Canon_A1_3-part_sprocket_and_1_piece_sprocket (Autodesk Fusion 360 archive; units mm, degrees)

design "Canon A1 3-part sprocket and 1 piece sprocket" references "Canon A1 Sprocket V2 real"
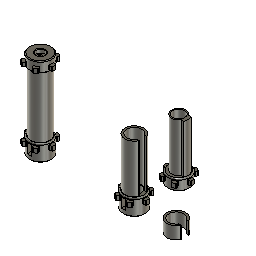
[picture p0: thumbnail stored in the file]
part number: 2026-03-01-16-37-55-654
sketch "Sketch1" plane through (0, 0, 0) normal (0, 0, 1) x axis (1, 0, 0)
  line L1 (4.3, 0) -> (4.5, 0)
  line L2 (4.45, 0) -> (4.3, 0)
  line L3 (5.6, 0.975) -> (4.45, 0.975)
  line L4 (5.6, -0.975) -> (5.6, 0.975)
  line L5 (4.45, -0.975) -> (5.6, -0.975)
  line L6 (4.3419, 0.975) -> (4.45, 0.975)
  line L7 (4.3419, -0.975) -> (4.45, -0.975)
  line L8 (5.6, 0.75) -> (5.6, 0)
  line L9 (4.6423, 0.975) -> (5.6, 0.75)
  line L10 (4.6423, -0.975) -> (5.6, -0.75)
  circle C1 centre (0, 0) radius 4.45
  circle C2 centre (0, 0) radius 1.725
  point P1 (0, 0)
  point P2 (0, 0)
  point P3 (0, 0)
  point P6 (4.45, 0)
  point P7 (4.45, 0.975)
  point P8 (4.45, -0.975)
  point P12 (4.3419, 0.975)
  point P13 (4.3419, -0.975)
  point P14 (5.6, 0)
  point P16 (4.6423, 0.975)
  point P15 (5.6, 0.75)
  point P17 (5.6, -0.75)
  point P18 (4.6423, -0.975)
  point P9 (5.6, 0.975)
  point P11 (4.45, -0.975)
  coincident P1 P2
  coincident P1 P3
  horizontal L1
  coincident L1 P6
  coincident C1 P6
  symmetric L1 P7 P8
  horizontal L3
  vertical L4
  horizontal L5
  coincident C1 P12
  coincident C1 P13
  midpoint L4 P14
  parallel L4 L8
  coincident L3 P16
  symmetric L1 P15 P17
  symmetric L1 P16 P18
  dimension "d1" diameter C1 = 8.9
  dimension "d2" diameter C2 = 3.45
  dimension "d3" distance P6 P7 = 0.975
  dimension "d4" distance P7 P9 = 1.15
  dimension "d5" distance P7 P11 = 1.95
  dimension "d6" distance P14 P15 = 0.75
extrude "Extrude1" new body sketch "Sketch1" profile of C1 C2 along normal blind 4.4
extrude "Extrude2" add sketch "Sketch1" profile of C1 L3 L4 L5 L6 L7 L8 L9 L10 along normal blind 0.85
extrude "Extrude3" add of existing geometry blind 1.7
extrude "Extrude4" cut sketch "Sketch1" profile of C1 L3 L4 L5 L6 L7 L8 L9 L10 along normal blind 0.5
extrude "Extrude5" cut of existing geometry blind -0.15
extrude "Extrude6" add of existing geometry blind 0.15
extrude "Extrude8" cut of existing geometry blind -0.15
extrude "Extrude9" cut of existing geometry blind -0.2
split "Split1"
fillet "Fillet1" radius 0.2
fillet "Fillet2" radius 1
circular_pattern "C-Pattern1" TotalAngle 360
extrude "Extrude10" add sketch "Sketch1" profile of C2 along normal blind 3
sketch "Sketch2" plane through (0, 0, 3) normal (0, 0, 1) x axis (-1, 0, 0)
  line L1 (-1.05, -0.7) -> (1.05, -0.7)
  line L2 (-1.05, 0.7) -> (-1.05, -0.7)
  line L3 (1.05, 0.7) -> (-1.05, 0.7)
  line L4 (1.05, -0.7) -> (1.05, 0.7)
  line L5 (-1.05, 0.7) -> (1.05, -0.7)
  line L6 (1.05, 0.7) -> (-1.05, -0.7)
  circle C1 centre (0, 0) radius 1.725
  point P7 (0, 0)
  point P2 (0, 0)
  point P5 (-1.05, 0.7)
  point P6 (1.05, 0.7)
  point P4 (-1.05, -0.7)
  horizontal L1
  perpendicular L1 L2
  parallel L1 L3
  parallel L2 L4
  coincident L5 P7
  coincident L6 P7
  coincident P2 P7
  dimension "d33" distance P5 P6 = 2.1
  dimension "d34" distance P4 P5 = 1.4
extrude "Extrude11" cut sketch "Sketch2" profile of L1 L2 L3 L4 against normal blind 6.8
fillet "Fillet3" radius 0.3
fillet "Fillet4" radius 0.3
fillet "Fillet5" radius 0.5
combine "Combine1"
copy_paste_bodies "CopyPasteBodies1"
move "Move1"
move "Move2"
align "Align1"
move "Move3"
sketch "Sketch3" plane through (0, 0, 4.4) normal (0, 0, 1) x axis (-1, 0, 0)
  line L1 (-1.05, 0.7) -> (-1.05, -0.7)
  line L2 (1.05, 0.7) -> (-1.05, 0.7)
  line L3 (1.05, -0.7) -> (1.05, 0.7)
  line L4 (-1.05, -0.7) -> (1.05, -0.7)
  circle C1 centre (0, 0) radius 3.95
  circle C2 centre (0, 0) radius 3.81
  concentric C1 C2
  dimension "d43" diameter C2 = 7.62
extrude "Extrude12" add sketch "Sketch3" profile of L1 L2 L3 L4 C2 along normal blind 26.7
sketch "Sketch4" plane through (0, 0, 0) normal (0, 0, -1) x axis (1, 0, 0)
  circle C1 centre (0, 0) radius 2.025
  circle C2 centre (0, 0) radius 4.15
  circle C3 centre (0, 0) radius 4.45
  circle C4 centre (0, 0) radius 3.6
  circle C5 centre (0, 0) radius 2.6
  point P1 (0, 0)
  point P3 (0, 0)
  coincident P1 P3
  dimension "d46" diameter C3 = 8.9
  dimension "d47" = -0.85
  dimension "d50" = -1
extrude "Extrude13" cut sketch "Sketch4" profile of C1 C4 against normal blind 0.92
delete_face "DeleteFace1"
extrude "Extrude14" cut sketch "Sketch4" profile of C1 C5 against normal blind 7
extrude "Extrude15" add of existing geometry blind 2.2
extrude "Extrude16" add of existing geometry blind 2.2
align "Align2"
move "Move4"
align "Align3"
delete_face "DeleteFace2"
split "Split2"
move "Move5"
extrude "Extrude17" cut of existing geometry blind -2.2
align "Align4"
combine "Combine2"
extrude "Extrude18" add of existing geometry blind 8.28
extrude "Extrude19" cut sketch "Sketch4" profile of C1 C5 against normal blind 32.5
sketch "Sketch5" plane through (0, 0, 0.92) normal (0, 0, -1) x axis (1, 0, 0)
  circle C1 centre (0, 0) radius 2.6
  circle C2 centre (0, 0) radius 3.6
  circle C3 centre (0, 0) radius 2.7
  dimension "d63" = 0.1
extrude "Extrude20" cut sketch "Sketch5" profile of C1 C3 against normal blind 31.58
sketch "Sketch6" plane through (0, 0, 0) normal (0, 0, -1) x axis (1, 0, 0)
  circle C1 centre (0, 0) radius 3.6
  circle C2 centre (0, 0) radius 4.45
sketch "Sketch7" plane through (0, 0, 5.75) normal (0, 0, 1) x axis (-1, 0, 0)
  line L1 (-3.0153, 3.2727) -> (-3.1076, 3.4325)
  line L2 (-1.4188, 4.4075) -> (-1.3266, 4.2477)
  line L3 (-2.042, 5.1093) -> (-1.5561, 4.5923)
  line L4 (-3.3123, 4.554) -> (-2.2877, 5.1455)
  line L5 (-3.199, 3.6438) -> (-3.4038, 4.323)
  arc A1 centre (-2.2415, 3.9325) radius 1 clockwise from (-3.1076, 3.4325) to (-3.199, 3.6438)
  arc A2 centre (0, 0) radius 4.45 clockwise from (-3.0153, 3.2727) to (-1.3266, 4.2477)
  arc A3 centre (-2.2848, 3.9075) radius 1 clockwise from (-1.5561, 4.5923) to (-1.4188, 4.4075)
  arc A4 centre (-2.1877, 4.9723) radius 0.2 clockwise from (-2.2877, 5.1455) to (-2.042, 5.1093)
  arc A5 centre (-3.2123, 4.3808) radius 0.2 clockwise from (-3.4038, 4.323) to (-3.3123, 4.554)
sketch "Sketch8" plane through (0, 0, 0) normal (0, 0, -1) x axis (1, 0, 0)
  line L1 (-0.85, 4.5) -> (0, 4.5)
  line L2 (0.85, 4.5) -> (-0.85, 4.5)
  line L3 (0.85, 2.2) -> (0.85, 4.5)
  line L4 (-0.85, 2.2) -> (0.85, 2.2)
  line L5 (-0.85, 4.5) -> (-0.85, 2.2)
  point P2 (0, 4.5)
  point P3 (-0.85, 4.5)
  point P4 (0.85, 4.5)
  horizontal L1
  horizontal L2
  vertical L3
  horizontal L4
  vertical L5
  dimension "d66" distance P2 P3 = 0.85
  dimension "d67" distance P3 P4 = 1.7
extrude "Extrude21" cut sketch "Sketch8" against normal blind 5.75
sketch "Sketch9" plane through (0, 0, 0) normal (0, 0, -1) x axis (1, 0, 0)
  line L1 (0.85, 3.4982) -> (0.85, 4.3681)
  line L2 (-0.85, 4.3681) -> (-0.85, 3.4982)
  arc A1 centre (0, 0) radius 3.6 clockwise from (0.85, 3.4982) to (-0.85, 3.4982)
  arc A2 centre (0, 0) radius 4.45 clockwise from (0.85, 4.3681) to (-0.85, 4.3681)
  circle C1 centre (0, 0) radius 4.45
  circle C2 centre (0, 0) radius 3.6
  concentric A1 C1
  concentric A1 C2
extrude "Extrude22" add sketch "Sketch9" profile of L1 L2 C1 C2 against normal blind 1.9
sketch "Sketch10" plane through (0, 0, 0.92) normal (0, 0, -1) x axis (1, 0, 0)
  line L1 (0.85, 2.5627) -> (0.85, 3.4982)
  line L2 (-0.85, 3.4982) -> (-0.85, 2.5627)
  arc A1 centre (0, 0) radius 2.7 clockwise from (0.85, 2.5627) to (-0.85, 2.5627)
  arc A2 centre (0, 0) radius 3.6 clockwise from (0.85, 3.4982) to (-0.85, 3.4982)
  circle C1 centre (0, 0) radius 2.7
  circle C2 centre (0, 0) radius 3.6
  point P1 (0, 0)
  point P7 (0, 0)
  coincident P1 P7
  concentric C1 C2
extrude "Extrude23" add sketch "Sketch10" profile of L1 L2 C1 C2 against normal blind 0.98
sketch "Sketch11" plane through (0, 0, 35.5) normal (0, 0, 1) x axis (-1, 0, 0)
  circle C1 centre (0, 0) radius 4.15
  circle C2 centre (0, 0) radius 1.725
  circle C3 centre (0, 0) radius 1.775
  dimension "d74" = 0.05
extrude "Extrude24" cut sketch "Sketch11" profile of C2 C3 against normal blind 1.4
fillet "Fillet6" radius 0.3
copy_paste_bodies "CopyPasteBodies2"
move "Move9"
sketch "Sketch12" plane through (0, 0, 0) normal (0, 1, 0) x axis (1, 0, 0)
  line L1 (0, -17.75) -> (0, 0)
  line L2 (0, -19.75) -> (0, -17.75)
  line L3 (0, -15.75) -> (0, -17.75)
  line L4 (5, -15.75) -> (0, -15.75)
  line L5 (-5, -19.75) -> (0, -19.75)
  point P1 (0, 0)
  point P2 (0, 0)
  point P3 (0, -17.75)
  point P4 (0, -19.75)
  point P5 (0, -15.75)
  coincident P1 P2
  vertical L1
  vertical L2
  parallel L1 L3
  perpendicular L1 L4
  perpendicular L2 L5
  dimension "d79" distance P2 P3 = 17.75
  dimension "d80" distance P3 P4 = 2
  dimension "d81" distance P3 P5 = 2
split "Split3"
move "Move6"
move "Move7"
align "Align5"
fillet "Fillet7" radius 0.3
chamfer "Chamfer1" distance 0.2
fillet "Fillet8" radius 0.2
move "Move8"
copy_paste_bodies "CopyPasteBodies3"
move "Move10"
split "Split4"
move "Move11"
align "Align6" sketch "Sketch10"
move "Move12"
extrude "Extrude25" cut of existing geometry blind -5
extrude "Extrude26" add of existing geometry blind 20.9
sketch "Sketch13" plane through (0, 0, 23.9) normal (0, 0, 1) x axis (-1, 0, 0)
  circle C1 centre (-38, -43) radius 3.81
  circle C2 centre (-38, -43) radius 2.7
  circle C3 centre (-38, -43) radius 2.1
  concentric C1 C3
  dimension "d91" diameter C3 = 4.2
extrude "Extrude27" add sketch "Sketch13" profile of C2 C3 against normal blind 20.9
sketch "Sketch14" plane through (0, 0, 27.5) normal (0, 0, 1) x axis (-1, 0, 0)
  circle C1 centre (-38, -25) radius 2.7
  circle C2 centre (-38, -25) radius 3.95
  circle C3 centre (-38, -25) radius 3
  concentric C1 C3
extrude "Extrude28" cut sketch "Sketch14" profile of C1 C3 against normal blind 20.9
sketch "Sketch15" plane through (0, 0, 23.9) normal (0, 0, 1) x axis (-1, 0, 0)
  line L1 (-40.4819, -44.5) -> (-41, -44.5)
  line L2 (-40.4819, -41.5) -> (-41, -41.5)
  line L3 (-41.5023, -41.5) -> (-41, -41.5)
  line L4 (-41.5023, -44.5) -> (-41, -44.5)
  circle C1 centre (-38, -43) radius 2.1
  circle C2 centre (-38, -43) radius 3.81
  circle C3 centre (-38, -43) radius 2.9
  circle C4 centre (-38, -43) radius 3.81
  point P5 (-40.4819, -44.5)
  point P7 (-40.4819, -41.5)
  point P8 (-41.5023, -41.5)
  point P9 (-41.5023, -44.5)
  concentric C1 C3
  coincident C3 P5
  horizontal L1
  coincident C3 P7
  parallel L1 L2
  coincident C2 P8
  parallel L2 L3
  coincident C2 P9
  parallel L1 L4
  concentric C3 C4
  dimension "d96" diameter C3 = 5.8
extrude "Extrude29" cut sketch "Sketch15" profile of C2 C3 L1 L2 L3 L4 C4 against normal blind 19.5
sketch "Sketch16" plane through (0, 0, 27.5) normal (0, 0, 1) x axis (-1, 0, 0)
  circle C1 centre (-38, -25) radius 3
  circle C2 centre (-38, -25) radius 3.95
sketch "Sketch17" plane through (0, 0, 27.5) normal (0, 0, 1) x axis (-1, 0, 0)
  circle C1 centre (-38, -25) radius 3.81
  circle C2 centre (-38, -25) radius 4.1773
  concentric C1 C2
  dimension "d99" diameter C1 = 7.62
extrude "Extrude30" cut sketch "Sketch17" profile of C1 against normal blind 20.9
extrude "Extrude31" add of existing geometry blind -20.9
sketch "Sketch18" plane through (0, 0, 27.5) normal (0, 0, 1) x axis (-1, 0, 0)
  line L1 (-40.5981, -26.5) -> (-41, -26.5)
  line L2 (-41.5023, -26.5) -> (-41, -26.5)
  line L3 (-40.5981, -23.5) -> (-41, -23.5)
  line L4 (-41.5023, -23.5) -> (-41, -23.5)
  line L5 (-41.5023, -26.6) -> (-41, -26.6)
  line L6 (-40.5981, -26.6) -> (-41, -26.6)
  line L7 (-40.5981, -23.4) -> (-41, -23.4)
  line L8 (-41.5023, -23.4) -> (-41, -23.4)
  line L9 (-40.5, -23.4) -> (-40.5981, -23.4)
  line L10 (-40.52, -26.6) -> (-40.5981, -26.6)
  circle C1 centre (-38, -25) radius 3.81
  circle C2 centre (-38, -25) radius 3
  point P5 (-40.5981, -26.5)
  point P6 (-41.5023, -26.5)
  point P8 (-40.5981, -23.5)
  point P9 (-41.5023, -23.5)
  coincident C2 P5
  horizontal L1
  coincident C1 P6
  parallel L1 L2
  coincident C2 P8
  parallel L2 L3
  coincident C1 P9
  parallel L3 L4
  parallel L7 L9
  parallel L6 L10
  dimension "d104" = -0.1
  dimension "d105" = -0.1
extrude "Extrude32" cut sketch "Sketch18" against normal blind 20.9
chamfer "Chamfer2" distance 0.1
chamfer "Chamfer3" distance 0.1
delete_face "DeleteFace3"
delete_face "DeleteFace4"
delete_face "DeleteFace5"
delete_face "DeleteFace6"
sketch "Sketch19" plane through (0, 0, 1.4) normal (0, 0, -1) x axis (1, 0, 0)
  line L1 (-15.95, 0.7) -> (-18.05, 0.7)
  line L2 (-15.95, -0.7) -> (-15.95, 0.7)
  line L3 (-18.05, -0.7) -> (-15.95, -0.7)
  line L4 (-18.05, 0.7) -> (-18.05, -0.7)
  line L5 (-16.05, 0.6) -> (-17.95, 0.6)
  line L6 (-16.05, -0.6) -> (-16.05, 0.6)
  line L7 (-17.95, -0.6) -> (-16.05, -0.6)
  line L8 (-17.95, 0.6) -> (-17.95, -0.6)
  circle C1 centre (-17, 0) radius 1.775
  dimension "d110" = 0.1
extrude "Extrude33" add sketch "Sketch19" profile of L1 L2 L3 L4 L5 L6 L7 L8 against normal blind 1.6
sketch "Sketch20" plane through (0, 0, 1.4) normal (0, 0, -1) x axis (1, 0, 0)
  line L1 (39.05, -43.7) -> (39.05, -42.3)
  line L2 (36.95, -43.7) -> (39.05, -43.7)
  line L3 (36.95, -42.3) -> (36.95, -43.7)
  line L4 (39.05, -42.3) -> (36.95, -42.3)
  line L5 (38.95, -42.4) -> (37.05, -42.4)
  line L6 (38.95, -43.6) -> (38.95, -42.4)
  line L7 (37.05, -43.6) -> (38.95, -43.6)
  line L8 (37.05, -42.4) -> (37.05, -43.6)
  circle C1 centre (38, -43) radius 1.775
  dimension "d113" = 0.1
extrude "Extrude34" add sketch "Sketch20" profile of L1 L2 L3 L4 L5 L6 L7 L8 against normal blind 1.6
chamfer "Chamfer4" distance 0.2
split "Split5"
copy_paste_bodies "CopyPasteBodies4"
move "Move13"
combine "Combine3"
extrude "Extrude35" cut of existing geometry blind -15.9
chamfer "Chamfer5" distance 0.4
extrude "Extrude36" cut of existing geometry blind -0.12
extrude "Extrude37" cut of existing geometry blind -1.4
align "Align7"
remove_body "RemoveBody1"
remove_body "RemoveBody2"
remove_body "RemoveBody3"
delete_face "DeleteFace7"
delete_face "DeleteFace8"
delete_face "DeleteFace9"
delete_face "DeleteFace10"
delete_face "DeleteFace11"
delete_face "DeleteFace12"
sketch "Sketch21" plane through (0, 0, 26.1) normal (0, 0, 1) x axis (-1, 0, 0)
  line L1 (-41.4578, -26.6) -> (-40.5377, -26.6)
  line L2 (-40.5377, -23.4) -> (-41.4578, -23.4)
  line L3 (-40.44, -23.5) -> (-41.3601, -23.5)
  line L4 (-41.4601, -26.5) -> (-40.5377, -26.5)
  line L5 (-41.5023, -23.5) -> (-41.3601, -23.5)
  line L6 (-41.5023, -26.5) -> (-41.4601, -26.5)
  line L7 (-41.5023, -26.5) -> (-40.5981, -26.5)
  arc A1 centre (-38, -25) radius 3 clockwise from (-40.5377, -23.4) to (-40.5377, -26.6)
  arc A2 centre (-38, -25) radius 3.81 clockwise from (-41.4578, -23.4) to (-41.4578, -26.6)
  circle C1 centre (-38, -25) radius 3
  circle C2 centre (-38, -25) radius 3.81
  point P14 (-41.5023, -23.5)
  point P15 (-41.5023, -26.5)
  point P16 (-40.5981, -26.5)
  concentric A2 C1
  concentric A1 C2
  coincident C2 P14
  parallel L3 L5
  coincident C2 P15
  parallel L4 L6
  coincident C1 P16
  coincident L4 P16
  dimension "d124" = 0.1
  dimension "d125" = 0.1
extrude "Extrude38" add sketch "Sketch21" profile of L1 L2 C1 C2 L3 L4 L5 L6 L7 against normal blind 19.5
fillet "Fillet9" radius 0.25
sketch "Sketch22" plane through (0, 0, 5) normal (0, 0, 1) x axis (-1, 0, 0)
  line L1 (-58.4578, -26.6) -> (-57.5377, -26.6)
  line L2 (-57.5377, -23.4) -> (-58.4578, -23.4)
  line L3 (-58.5023, -26.5) -> (-58, -26.5)
  line L4 (-57.5981, -26.5) -> (-58, -26.5)
  line L5 (-58.5023, -23.5) -> (-58, -23.5)
  line L6 (-57.5981, -23.5) -> (-58, -23.5)
  arc A1 centre (-55, -25) radius 3 clockwise from (-57.5377, -23.4) to (-57.5377, -26.6)
  arc A2 centre (-55, -25) radius 3.81 clockwise from (-58.4578, -23.4) to (-58.4578, -26.6)
  circle C1 centre (-55, -25) radius 3
  circle C2 centre (-55, -25) radius 3.81
  point P2 (-57.5377, -26.6)
  point P5 (-58.4578, -26.6)
  point P11 (-58.5023, -26.5)
  point P12 (-57.5981, -26.5)
  point P14 (-58.5023, -23.5)
  point P15 (-57.5981, -23.5)
  concentric A2 C1
  coincident P2 C1
  concentric A1 C2
  coincident P5 C2
  coincident C2 P11
  horizontal L3
  coincident C1 P12
  parallel L3 L4
  coincident C2 P14
  parallel L4 L5
  coincident C1 P15
  parallel L5 L6
extrude "Extrude39" add sketch "Sketch22" profile of L1 L2 C1 C2 L3 L4 L5 L6 against normal blind 5
fillet "Fillet10" radius 0.25
delete_face "DeleteFace13"
sketch "Sketch23" plane through (0, 0, 0) normal (0, 0, -1) x axis (1, 0, 0)
  circle C1 centre (38, -43) radius 4.15
  circle C2 centre (38, -43) radius 1.775
  circle C3 centre (38, -43) radius 1.825
  dimension "d134" = 0.05
extrude "Extrude40" cut sketch "Sketch23" profile of C2 C3 against normal blind 1.4
sketch "Sketch24" plane through (0, 0, 1.4) normal (0, 0, -1) x axis (1, 0, 0)
  line L1 (37.05, -42.4) -> (37.05, -43.6)
  line L2 (38.95, -42.4) -> (37.05, -42.4)
  line L3 (38.95, -43.6) -> (38.95, -42.4)
  line L4 (37.05, -43.6) -> (38.95, -43.6)
  line L5 (39, -42.35) -> (37, -42.35)
  line L6 (39, -43.65) -> (39, -42.35)
  line L7 (37, -43.65) -> (39, -43.65)
  line L8 (37, -42.35) -> (37, -43.65)
  circle C1 centre (38, -43) radius 1.825
  dimension "d137" = -0.05
extrude "Extrude41" cut sketch "Sketch24" profile of L1 L2 L3 L4 L5 L8 L6 L7 against normal blind 1.8
chamfer "Chamfer7" distance 0.2
sketch "Sketch25" plane through (0, 0, 0) normal (0, 0, -1) x axis (1, 0, 0)
  circle C1 centre (38, -25) radius 3.6
  circle C2 centre (38, -25) radius 4.15
  circle C3 centre (38, -25) radius 3.65
  dimension "d142" = 0.05
extrude "Extrude42" cut sketch "Sketch25" profile of C1 C3 against normal blind 0.92
extrude "Extrude43" cut of existing geometry blind -0.1
chamfer "Chamfer8" distance 0.2
sketch "Sketch26" plane through (0, 0, 23.9) normal (0, 0, 1) x axis (-1, 0, 0)
  line L1 (-40.4819, -44.5) -> (-41.5023, -44.5)
  line L2 (-41.5023, -41.5) -> (-40.4819, -41.5)
  arc A1 centre (-38, -43) radius 3.81 clockwise from (-41.5023, -44.5) to (-41.5023, -41.5)
  arc A2 centre (-38, -43) radius 2.9 clockwise from (-40.4819, -41.5) to (-40.4819, -44.5)
  circle C1 centre (-38, -43) radius 2.1
  arc A3 centre (-38, -43) radius 2.4 clockwise from (-40.054, -41.7586) to (-40.054, -44.2414)
  circle C2 centre (-38, -43) radius 2.4
  concentric A1 C2
  dimension "d148" = -0.5
extrude "Extrude44" cut sketch "Sketch26" profile of C1 A3 C2 against normal blind 20.9
external_derived "ExternalDerived1"
extrude "Extrude45" cut of existing geometry blind -0.12
sketch "Sketch27" plane through (0, 0, 0) normal (0, 0, -1) x axis (1, 0, 0)
  circle C1 centre (0, -25) radius 3.6
  circle C2 centre (0, -25) radius 4.15
  circle C3 centre (0, -25) radius 3.65
  dimension "d153" = 0.05
extrude "Extrude46" cut sketch "Sketch27" profile of C1 C3 against normal blind 0.92
extrude "Extrude47" cut of existing geometry blind -0.1
sketch "Sketch28" plane through (0, 0, 35.5) normal (0, 0, 1) x axis (-1, 0, 0)
  circle C1 centre (0, -25) radius 1.775
  circle C2 centre (0, -25) radius 4.15
  circle C3 centre (0, -25) radius 1.825
  dimension "d158" = 0.05
extrude "Extrude48" cut sketch "Sketch28" profile of C1 C3 against normal blind 1.5
chamfer "Chamfer9" distance 0.2
sketch "Sketch29" plane through (0, 0, 34) normal (0, 0, 1) x axis (-1, 0, 0)
  line L1 (-1.05, -24.3) -> (-1.05, -25.7)
  line L2 (1.05, -24.3) -> (-1.05, -24.3)
  line L3 (1.05, -25.7) -> (1.05, -24.3)
  line L4 (-1.05, -25.7) -> (1.05, -25.7)
  line L5 (1, -24.35) -> (-1, -24.35)
  line L6 (1, -25.65) -> (1, -24.35)
  line L7 (-1, -25.65) -> (1, -25.65)
  line L8 (-1, -24.35) -> (-1, -25.65)
  circle C1 centre (0, -25) radius 1.825
  dimension "d162" = 0.05
extrude "Extrude49" add sketch "Sketch29" profile of L1 L2 L3 L4 L7 L5 L6 L8 against normal blind 1.5
chamfer "Chamfer10" distance 0.2
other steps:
base_feature "Base Feature1"
base_feature "Base Feature2"
base_feature "Base Feature3"
base_feature "Base Feature4"
derived_base_feature "Derived Base Feature"

design "Canon A1 Sprocket V2 real"
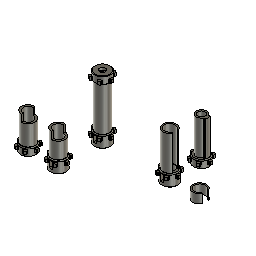
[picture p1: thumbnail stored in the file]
part number: 2026-03-01-16-37-55-654
sketch "Sketch1" plane through (0, 0, 0) normal (0, 0, 1) x axis (1, 0, 0)
  line L1 (4.3, 0) -> (4.5, 0)
  line L2 (4.45, 0) -> (4.3, 0)
  line L3 (5.6, 0.975) -> (4.45, 0.975)
  line L4 (5.6, -0.975) -> (5.6, 0.975)
  line L5 (4.45, -0.975) -> (5.6, -0.975)
  line L6 (4.3419, 0.975) -> (4.45, 0.975)
  line L7 (4.3419, -0.975) -> (4.45, -0.975)
  line L8 (5.6, 0.75) -> (5.6, 0)
  line L9 (4.6423, 0.975) -> (5.6, 0.75)
  line L10 (4.6423, -0.975) -> (5.6, -0.75)
  circle C1 centre (0, 0) radius 4.45
  circle C2 centre (0, 0) radius 1.725
  point P1 (0, 0)
  point P2 (0, 0)
  point P3 (0, 0)
  point P6 (4.45, 0)
  point P7 (4.45, 0.975)
  point P8 (4.45, -0.975)
  point P12 (4.3419, 0.975)
  point P13 (4.3419, -0.975)
  point P14 (5.6, 0)
  point P16 (4.6423, 0.975)
  point P15 (5.6, 0.75)
  point P17 (5.6, -0.75)
  point P18 (4.6423, -0.975)
  point P9 (5.6, 0.975)
  point P11 (4.45, -0.975)
  coincident P1 P2
  coincident P1 P3
  horizontal L1
  coincident L1 P6
  coincident C1 P6
  symmetric L1 P7 P8
  horizontal L3
  vertical L4
  horizontal L5
  coincident C1 P12
  coincident C1 P13
  midpoint L4 P14
  parallel L4 L8
  coincident L3 P16
  symmetric L1 P15 P17
  symmetric L1 P16 P18
  dimension "d1" diameter C1 = 8.9
  dimension "d2" diameter C2 = 3.45
  dimension "d3" distance P6 P7 = 0.975
  dimension "d4" distance P7 P9 = 1.15
  dimension "d5" distance P7 P11 = 1.95
  dimension "d6" distance P14 P15 = 0.75
extrude "Extrude1" new body sketch "Sketch1" profile of C1 C2 along normal blind 4.4
extrude "Extrude2" add sketch "Sketch1" profile of C1 L3 L4 L5 L6 L7 L8 L9 L10 along normal blind 0.85
extrude "Extrude3" add of existing geometry blind 1.7
extrude "Extrude4" cut sketch "Sketch1" profile of C1 L3 L4 L5 L6 L7 L8 L9 L10 along normal blind 0.5
extrude "Extrude5" cut of existing geometry blind -0.15
extrude "Extrude6" add of existing geometry blind 0.15
extrude "Extrude8" cut of existing geometry blind -0.15
extrude "Extrude9" cut of existing geometry blind -0.2
split "Split1"
fillet "Fillet1" radius 0.2
fillet "Fillet2" radius 1
circular_pattern "C-Pattern1" TotalAngle 360
extrude "Extrude10" add sketch "Sketch1" profile of C2 along normal blind 3
sketch "Sketch2" plane through (0, 0, 3) normal (0, 0, 1) x axis (-1, 0, 0)
  line L1 (-1.05, -0.7) -> (1.05, -0.7)
  line L2 (-1.05, 0.7) -> (-1.05, -0.7)
  line L3 (1.05, 0.7) -> (-1.05, 0.7)
  line L4 (1.05, -0.7) -> (1.05, 0.7)
  line L5 (-1.05, 0.7) -> (1.05, -0.7)
  line L6 (1.05, 0.7) -> (-1.05, -0.7)
  circle C1 centre (0, 0) radius 1.725
  point P7 (0, 0)
  point P2 (0, 0)
  point P5 (-1.05, 0.7)
  point P6 (1.05, 0.7)
  point P4 (-1.05, -0.7)
  horizontal L1
  perpendicular L1 L2
  parallel L1 L3
  parallel L2 L4
  coincident L5 P7
  coincident L6 P7
  coincident P2 P7
  dimension "d33" distance P5 P6 = 2.1
  dimension "d34" distance P4 P5 = 1.4
extrude "Extrude11" cut sketch "Sketch2" profile of L1 L2 L3 L4 against normal blind 6.8
fillet "Fillet3" radius 0.3
fillet "Fillet4" radius 0.3
fillet "Fillet5" radius 0.5
combine "Combine1"
copy_paste_bodies "CopyPasteBodies1"
move "Move1"
move "Move2"
align "Align1"
move "Move3"
sketch "Sketch3" plane through (0, 0, 4.4) normal (0, 0, 1) x axis (-1, 0, 0)
  line L1 (-1.05, 0.7) -> (-1.05, -0.7)
  line L2 (1.05, 0.7) -> (-1.05, 0.7)
  line L3 (1.05, -0.7) -> (1.05, 0.7)
  line L4 (-1.05, -0.7) -> (1.05, -0.7)
  circle C1 centre (0, 0) radius 3.95
  circle C2 centre (0, 0) radius 3.81
  concentric C1 C2
  dimension "d43" diameter C2 = 7.62
extrude "Extrude12" add sketch "Sketch3" profile of L1 L2 L3 L4 C2 along normal blind 26.7
sketch "Sketch4" plane through (0, 0, 0) normal (0, 0, -1) x axis (1, 0, 0)
  circle C1 centre (0, 0) radius 2.025
  circle C2 centre (0, 0) radius 4.15
  circle C3 centre (0, 0) radius 4.45
  circle C4 centre (0, 0) radius 3.6
  circle C5 centre (0, 0) radius 2.6
  point P1 (0, 0)
  point P3 (0, 0)
  coincident P1 P3
  dimension "d46" diameter C3 = 8.9
  dimension "d47" = -0.85
  dimension "d50" = -1
extrude "Extrude13" cut sketch "Sketch4" profile of C1 C4 against normal blind 0.92
delete_face "DeleteFace1"
extrude "Extrude14" cut sketch "Sketch4" profile of C1 C5 against normal blind 7
extrude "Extrude15" add of existing geometry blind 2.2
extrude "Extrude16" add of existing geometry blind 2.2
align "Align2"
move "Move4"
align "Align3"
delete_face "DeleteFace2"
split "Split2"
move "Move5"
extrude "Extrude17" cut of existing geometry blind -2.2
align "Align4"
combine "Combine2"
extrude "Extrude18" add of existing geometry blind 8.28
extrude "Extrude19" cut sketch "Sketch4" profile of C1 C5 against normal blind 32.5
sketch "Sketch5" plane through (0, 0, 0.92) normal (0, 0, -1) x axis (1, 0, 0)
  circle C1 centre (0, 0) radius 2.6
  circle C2 centre (0, 0) radius 3.6
  circle C3 centre (0, 0) radius 2.7
  dimension "d63" = 0.1
extrude "Extrude20" cut sketch "Sketch5" profile of C1 C3 against normal blind 31.58
sketch "Sketch6" plane through (0, 0, 0) normal (0, 0, -1) x axis (1, 0, 0)
  circle C1 centre (0, 0) radius 3.6
  circle C2 centre (0, 0) radius 4.45
sketch "Sketch7" plane through (0, 0, 5.75) normal (0, 0, 1) x axis (-1, 0, 0)
  line L1 (-3.0153, 3.2727) -> (-3.1076, 3.4325)
  line L2 (-1.4188, 4.4075) -> (-1.3266, 4.2477)
  line L3 (-2.042, 5.1093) -> (-1.5561, 4.5923)
  line L4 (-3.3123, 4.554) -> (-2.2877, 5.1455)
  line L5 (-3.199, 3.6438) -> (-3.4038, 4.323)
  arc A1 centre (-2.2415, 3.9325) radius 1 clockwise from (-3.1076, 3.4325) to (-3.199, 3.6438)
  arc A2 centre (0, 0) radius 4.45 clockwise from (-3.0153, 3.2727) to (-1.3266, 4.2477)
  arc A3 centre (-2.2848, 3.9075) radius 1 clockwise from (-1.5561, 4.5923) to (-1.4188, 4.4075)
  arc A4 centre (-2.1877, 4.9723) radius 0.2 clockwise from (-2.2877, 5.1455) to (-2.042, 5.1093)
  arc A5 centre (-3.2123, 4.3808) radius 0.2 clockwise from (-3.4038, 4.323) to (-3.3123, 4.554)
sketch "Sketch8" plane through (0, 0, 0) normal (0, 0, -1) x axis (1, 0, 0)
  line L1 (-0.85, 4.5) -> (0, 4.5)
  line L2 (0.85, 4.5) -> (-0.85, 4.5)
  line L3 (0.85, 2.2) -> (0.85, 4.5)
  line L4 (-0.85, 2.2) -> (0.85, 2.2)
  line L5 (-0.85, 4.5) -> (-0.85, 2.2)
  point P2 (0, 4.5)
  point P3 (-0.85, 4.5)
  point P4 (0.85, 4.5)
  horizontal L1
  horizontal L2
  vertical L3
  horizontal L4
  vertical L5
  dimension "d66" distance P2 P3 = 0.85
  dimension "d67" distance P3 P4 = 1.7
extrude "Extrude21" cut sketch "Sketch8" against normal blind 5.75
sketch "Sketch9" plane through (0, 0, 0) normal (0, 0, -1) x axis (1, 0, 0)
  line L1 (0.85, 3.4982) -> (0.85, 4.3681)
  line L2 (-0.85, 4.3681) -> (-0.85, 3.4982)
  arc A1 centre (0, 0) radius 3.6 clockwise from (0.85, 3.4982) to (-0.85, 3.4982)
  arc A2 centre (0, 0) radius 4.45 clockwise from (0.85, 4.3681) to (-0.85, 4.3681)
  circle C1 centre (0, 0) radius 4.45
  circle C2 centre (0, 0) radius 3.6
  concentric A1 C1
  concentric A1 C2
extrude "Extrude22" add sketch "Sketch9" profile of L1 L2 C1 C2 against normal blind 1.9
sketch "Sketch10" plane through (0, 0, 0.92) normal (0, 0, -1) x axis (1, 0, 0)
  line L1 (0.85, 2.5627) -> (0.85, 3.4982)
  line L2 (-0.85, 3.4982) -> (-0.85, 2.5627)
  arc A1 centre (0, 0) radius 2.7 clockwise from (0.85, 2.5627) to (-0.85, 2.5627)
  arc A2 centre (0, 0) radius 3.6 clockwise from (0.85, 3.4982) to (-0.85, 3.4982)
  circle C1 centre (0, 0) radius 2.7
  circle C2 centre (0, 0) radius 3.6
  point P1 (0, 0)
  point P7 (0, 0)
  coincident P1 P7
  concentric C1 C2
extrude "Extrude23" add sketch "Sketch10" profile of L1 L2 C1 C2 against normal blind 0.98
sketch "Sketch11" plane through (0, 0, 35.5) normal (0, 0, 1) x axis (-1, 0, 0)
  circle C1 centre (0, 0) radius 4.15
  circle C2 centre (0, 0) radius 1.725
  circle C3 centre (0, 0) radius 1.775
  dimension "d74" = 0.05
extrude "Extrude24" cut sketch "Sketch11" profile of C2 C3 against normal blind 1.4
fillet "Fillet6" radius 0.3
copy_paste_bodies "CopyPasteBodies2"
move "Move9"
sketch "Sketch12" plane through (0, 0, 0) normal (0, 1, 0) x axis (1, 0, 0)
  line L1 (0, -17.75) -> (0, 0)
  line L2 (0, -19.75) -> (0, -17.75)
  line L3 (0, -15.75) -> (0, -17.75)
  line L4 (5, -15.75) -> (0, -15.75)
  line L5 (-5, -19.75) -> (0, -19.75)
  point P1 (0, 0)
  point P2 (0, 0)
  point P3 (0, -17.75)
  point P4 (0, -19.75)
  point P5 (0, -15.75)
  coincident P1 P2
  vertical L1
  vertical L2
  parallel L1 L3
  perpendicular L1 L4
  perpendicular L2 L5
  dimension "d79" distance P2 P3 = 17.75
  dimension "d80" distance P3 P4 = 2
  dimension "d81" distance P3 P5 = 2
split "Split3"
move "Move6"
move "Move7"
align "Align5"
fillet "Fillet7" radius 0.3
chamfer "Chamfer1" distance 0.2
fillet "Fillet8" radius 0.2
move "Move8"
copy_paste_bodies "CopyPasteBodies3"
move "Move10"
split "Split4"
move "Move11"
align "Align6" sketch "Sketch10"
move "Move12"
extrude "Extrude25" cut of existing geometry blind -5
extrude "Extrude26" add of existing geometry blind 20.9
sketch "Sketch13" plane through (0, 0, 23.9) normal (0, 0, 1) x axis (-1, 0, 0)
  circle C1 centre (-38, -43) radius 3.81
  circle C2 centre (-38, -43) radius 2.7
  circle C3 centre (-38, -43) radius 2.1
  concentric C1 C3
  dimension "d91" diameter C3 = 4.2
extrude "Extrude27" add sketch "Sketch13" profile of C2 C3 against normal blind 20.9
sketch "Sketch14" plane through (0, 0, 27.5) normal (0, 0, 1) x axis (-1, 0, 0)
  circle C1 centre (-38, -25) radius 2.7
  circle C2 centre (-38, -25) radius 3.95
  circle C3 centre (-38, -25) radius 3
  concentric C1 C3
extrude "Extrude28" cut sketch "Sketch14" profile of C1 C3 against normal blind 20.9
sketch "Sketch15" plane through (0, 0, 23.9) normal (0, 0, 1) x axis (-1, 0, 0)
  line L1 (-40.4819, -44.5) -> (-41, -44.5)
  line L2 (-40.4819, -41.5) -> (-41, -41.5)
  line L3 (-41.5023, -41.5) -> (-41, -41.5)
  line L4 (-41.5023, -44.5) -> (-41, -44.5)
  circle C1 centre (-38, -43) radius 2.1
  circle C2 centre (-38, -43) radius 3.81
  circle C3 centre (-38, -43) radius 2.9
  circle C4 centre (-38, -43) radius 3.81
  point P5 (-40.4819, -44.5)
  point P7 (-40.4819, -41.5)
  point P8 (-41.5023, -41.5)
  point P9 (-41.5023, -44.5)
  concentric C1 C3
  coincident C3 P5
  horizontal L1
  coincident C3 P7
  parallel L1 L2
  coincident C2 P8
  parallel L2 L3
  coincident C2 P9
  parallel L1 L4
  concentric C3 C4
  dimension "d96" diameter C3 = 5.8
extrude "Extrude29" cut sketch "Sketch15" profile of C2 C3 L1 L2 L3 L4 C4 against normal blind 19.5
sketch "Sketch16" plane through (0, 0, 27.5) normal (0, 0, 1) x axis (-1, 0, 0)
  circle C1 centre (-38, -25) radius 3
  circle C2 centre (-38, -25) radius 3.95
sketch "Sketch17" plane through (0, 0, 27.5) normal (0, 0, 1) x axis (-1, 0, 0)
  circle C1 centre (-38, -25) radius 3.81
  circle C2 centre (-38, -25) radius 4.1773
  concentric C1 C2
  dimension "d99" diameter C1 = 7.62
extrude "Extrude30" cut sketch "Sketch17" profile of C1 against normal blind 20.9
extrude "Extrude31" add of existing geometry blind -20.9
sketch "Sketch18" plane through (0, 0, 27.5) normal (0, 0, 1) x axis (-1, 0, 0)
  line L1 (-40.5981, -26.5) -> (-41, -26.5)
  line L2 (-41.5023, -26.5) -> (-41, -26.5)
  line L3 (-40.5981, -23.5) -> (-41, -23.5)
  line L4 (-41.5023, -23.5) -> (-41, -23.5)
  line L5 (-41.5023, -26.6) -> (-41, -26.6)
  line L6 (-40.5981, -26.6) -> (-41, -26.6)
  line L7 (-40.5981, -23.4) -> (-41, -23.4)
  line L8 (-41.5023, -23.4) -> (-41, -23.4)
  line L9 (-40.5, -23.4) -> (-40.5981, -23.4)
  line L10 (-40.52, -26.6) -> (-40.5981, -26.6)
  circle C1 centre (-38, -25) radius 3.81
  circle C2 centre (-38, -25) radius 3
  point P5 (-40.5981, -26.5)
  point P6 (-41.5023, -26.5)
  point P8 (-40.5981, -23.5)
  point P9 (-41.5023, -23.5)
  coincident C2 P5
  horizontal L1
  coincident C1 P6
  parallel L1 L2
  coincident C2 P8
  parallel L2 L3
  coincident C1 P9
  parallel L3 L4
  parallel L7 L9
  parallel L6 L10
  dimension "d104" = -0.1
  dimension "d105" = -0.1
extrude "Extrude32" cut sketch "Sketch18" against normal blind 20.9
chamfer "Chamfer2" distance 0.1
chamfer "Chamfer3" distance 0.1
delete_face "DeleteFace3"
delete_face "DeleteFace4"
delete_face "DeleteFace5"
delete_face "DeleteFace6"
sketch "Sketch19" plane through (0, 0, 1.4) normal (0, 0, -1) x axis (1, 0, 0)
  line L1 (-15.95, 0.7) -> (-18.05, 0.7)
  line L2 (-15.95, -0.7) -> (-15.95, 0.7)
  line L3 (-18.05, -0.7) -> (-15.95, -0.7)
  line L4 (-18.05, 0.7) -> (-18.05, -0.7)
  line L5 (-16.05, 0.6) -> (-17.95, 0.6)
  line L6 (-16.05, -0.6) -> (-16.05, 0.6)
  line L7 (-17.95, -0.6) -> (-16.05, -0.6)
  line L8 (-17.95, 0.6) -> (-17.95, -0.6)
  circle C1 centre (-17, 0) radius 1.775
  dimension "d110" = 0.1
extrude "Extrude33" add sketch "Sketch19" profile of L1 L2 L3 L4 L5 L6 L7 L8 against normal blind 1.6
sketch "Sketch20" plane through (0, 0, 1.4) normal (0, 0, -1) x axis (1, 0, 0)
  line L1 (39.05, -43.7) -> (39.05, -42.3)
  line L2 (36.95, -43.7) -> (39.05, -43.7)
  line L3 (36.95, -42.3) -> (36.95, -43.7)
  line L4 (39.05, -42.3) -> (36.95, -42.3)
  line L5 (38.95, -42.4) -> (37.05, -42.4)
  line L6 (38.95, -43.6) -> (38.95, -42.4)
  line L7 (37.05, -43.6) -> (38.95, -43.6)
  line L8 (37.05, -42.4) -> (37.05, -43.6)
  circle C1 centre (38, -43) radius 1.775
  dimension "d113" = 0.1
extrude "Extrude34" add sketch "Sketch20" profile of L1 L2 L3 L4 L5 L6 L7 L8 against normal blind 1.6
chamfer "Chamfer4" distance 0.2
split "Split5"
copy_paste_bodies "CopyPasteBodies4"
move "Move13"
combine "Combine3"
extrude "Extrude35" cut of existing geometry blind -15.9
chamfer "Chamfer5" distance 0.4
extrude "Extrude36" cut of existing geometry blind -0.12
extrude "Extrude37" cut of existing geometry blind -1.4
align "Align7"
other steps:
base_feature "Base Feature1"
base_feature "Base Feature2"
base_feature "Base Feature3"
base_feature "Base Feature4"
